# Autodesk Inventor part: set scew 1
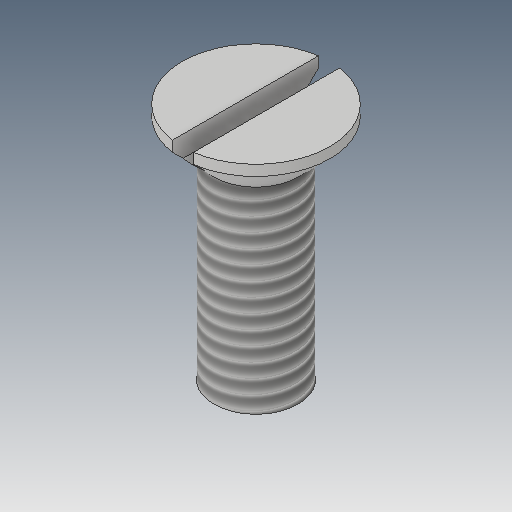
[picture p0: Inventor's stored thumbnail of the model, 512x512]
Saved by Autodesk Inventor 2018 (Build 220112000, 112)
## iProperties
Created: 2016-06
Part Number: set scew 1
Material: Generic
Document SubType Name: Modeling
Designer: CADCIM
Density: 1 g/cm^3
Appearance: Default
Mass: 0.577668 g
Surface Area: 5.12671 cm^2
Volume: 0.577668 cm^3
Author: CADCIM
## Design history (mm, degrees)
sketch "Sketch1"
  geometry: C1 r 3 at (0, 0); 1 further point
  constraints: 1 centre point, 1 coincident
  dimensions: "d0" = 6 diameter of C1
extrude "Extrusion1" new body sketch "Sketch1" distance "d1" = 14; taper "d2" = 0 deg
sketch "Sketch2"
  geometry: L1 (14, -3)-(14, 3) reference; L2 (14, 0)-(14, -3); L3 (14, -3)-(17, -6); L4 (17, -6)-(17, 0); L5 (17, 0)-(14, 0); 1 further point
  constraints: 8 end point, 2 vertical, 1 midpoint, 1 perpendicular
  dimensions: "d4" = 3 distance of L2.start L2.end; "d5" = 6 distance of L4.end L3.end; "d6" = 3 distance from line of L1.start L4
revolve "Revolution1" sketch "Sketch2" stored, may be unused: angle "d7" = 90 deg
sketch "Sketch3"
  geometry: C1 r 5.25 at (0, 0); 1 further point
  constraints: 1 centre point, 1 coincident
  dimensions: "d8" = 10.5 diameter of C1
extrude "Extrusion2" sketch "Sketch3" distance "d9" = 26.75; taper "d10" = 0 deg
sketch "Sketch4"
  geometry: L1 (-0.75, 8.347)-(0.75, 8.347); L2 (0.75, 8.347)-(0.75, -8.125); L3 (0.75, -8.125)-(-0.75, -8.125); L4 (-0.75, -8.125)-(-0.75, 8.347); L5 (0, 0)-(0, 6.165)
  constraints: 10 end point, 3 parallel, 1 horizontal, 1 perpendicular, 1 other
  dimensions: "d11" = 1.5 distance of L1.start L1.end
extrude "Extrusion3" cut sketch "Sketch4" distance "d12" = 1.5; taper "d13" = 0 deg
sketch "Sketch5"
  geometry: L1 (0, 0)-(0, 3); L2 (0, 3)-(-1.732, 0); L3 (-1.732, 0)-(0, 0); L4 (0, 3)-(0, -3) reference; 1 further point
  constraints: 6 end point, 2 midpoint, 1 perpendicular, 1 point on line, 1 vertical
  dimensions: "d21" = 60 deg angle of L2 L3; "d22" = 3 distance of L1.start L1.end
thread "Thread2" dims "d19" = 10, "d20" = 0
revolve "Revolution3" stored, may be unused: angle "d23" = 90 deg
body "Solid1"
